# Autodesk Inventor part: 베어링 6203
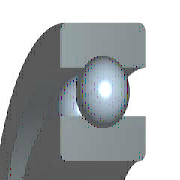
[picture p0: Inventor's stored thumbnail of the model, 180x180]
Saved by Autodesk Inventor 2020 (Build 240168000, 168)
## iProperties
Created: 2012-02
Part Number: 베어링 6203
Material: 강철, 연강
Description: 깊은 그루브 볼 베어링
Document SubType Name: Modeling
Standard: KS B 2023
Designer: mduedu
Standards Organization: KS
Language: ko-KR
Size Designation: 6203 - 17 x 40 x 12
Categories: <MemberInstance><Categories><Category DisplayName="샤프트 부품" InternalName="7f7aeb1f-a693-4053-b835-cee3144e0d98" Mnemonic="SHFT"><Category DisplayName="베어링" Inter
Density: 1 g/cm^3
Appearance: 노란색
IsCustomPart: 1
Author: mduedu
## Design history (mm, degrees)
sketch "스케치" dims "d0" = 5.98 (= -0.26 x WD + 0.26 x BD)
  geometry: L1 (3.01, 14.25)-(8.99, 14.25); L2 (6, 14.25)-(6, 11.26); L3 (6, 14.25)-(6, 17.24); L4 (3.778, 12.249)-(0, 12.249); L5 (0, 8.5)-(12, 8.5); L6 (3.778, 16.251)-(0, 16.251); L7 (0, 20)-(12, 20); L8 (12, 8.5)-(12, 12.249); L9 (8.222, 12.249)-(12, 12.249); L10 (8.222, 16.251)-(12, 16.251); L11 (12, 20)-(12, 16.251); L12 (-1.4, 0)-(8.4, 0) reference; L13 (0, -0.3)-(0, 5.3) reference
  constraints: 22 end point, 4 point on line, 2 collinear, 2 perpendicular, 2 symmetric about line, 1 midpoint, 1 parallel, 14 other
  dimensions: "d9" = 17 diameter of L5 L12 (= WD); "d11" = 40 diameter of L7 L12 (= BD); "d12" = 12 distance between parallel lines of L8 L13 (= KB); "d13" = 24.498 diameter of L9 L12 (= 0.326 x BD + 0.674 x WD)
revolve "본체" stored, may be unused: angle "d6" = 90 deg
revolve "볼" stored, may be unused: angle "d7" = 90 deg
pattern_circular "IDS_ARRAYBALL[SIMPL:T]" dims angle "d3" = 360 deg
body "Solid1"
fillet "모깎기1" dims "d1" = 0.6 (= KRS)
other parameters: "WD" = 17 [user parameter; used in 5 equation terms], "BD" = 40 [user parameter; used in 5 equation terms], "KB" = 12 [user parameter; used in 1 equation term], "KRS" = 0.6 [user parameter; used in 1 equation term], "d4" = 0, "d5" = 0, "d8" = 0, "d14" = 0, "d15" = 0, "BBA" = 0 [user parameter], "BC0" = 4750000 [user parameter], "BC" = 9560000 [user parameter], "WR" = 8.5 (= 0.5 x WD) [user parameter]
